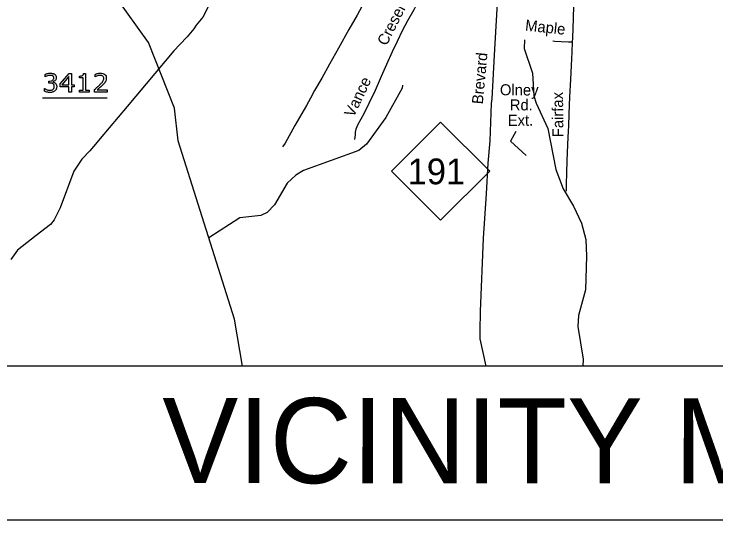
# Model space of a CAD drawing. Extents: x 925297 to 940193, y 663541 to 689899.
# Drawn here: x 927782 to 928734, y 687191 to 687878 of the extents above; entities that cross this region are included whole.
import ezdxf

# ---------------------------------------------------------------- set-up
doc = ezdxf.new("R2010")
doc.units = 0
doc.layers.add('Default', color=7, linetype='Continuous')
doc.layers.add('Sheet Title CELL', color=7, linetype='Continuous')

msp = doc.modelspace()

# ---------------------------------------------------------------- linework, layer by layer
at = {"layer": 'Default'}
msp.add_line((927820.41, 687764.45), (927908.02, 687764.45), dxfattribs=at)
for points in [[(928091.65, 687400.3), (928081, 687464), (928004.68, 687706.39), (927999.58, 687750.47), (927964.39, 687839.77), (927889.77, 687944.3), (927840.93, 688024.69), (927845.58, 688107.96), (927839.62, 688127.77), (927820.71, 688158.34), (927785.15, 688236.49), (927782.3, 688250.33)], [(928422.69, 687400.3), (928414.19, 687437.24), (928414.42, 687448.07), (928414.77, 687474.32), (928419.06, 687574.19), (928422.79, 687634.18), (928425.12, 687675.86), (928427.91, 687706.32), (928429.77, 687756.68), (928430.82, 687763.14), (928433.64, 687822.45), (928441.53, 687956.48), (928442.81, 687994.5), (928444.79, 688004.27), (928451.77, 688016.8), (928473.2, 688057.64), (928484.27, 688085)], [(928547.33, 688006.84), (928547.12, 688001.43), (928545.43, 687972.42), (928544.67, 687955.24), (928543.15, 687930.23), (928542.13, 687908.37), (928541.14, 687889.77), (928540.37, 687872.33), (928539.47, 687845.93), (928539.19, 687840.09)], [(928340.72, 687929.8), (928339.01, 687924.22), (928334.57, 687910.76), (928330.26, 687895.79), (928324.28, 687884), (928315.88, 687869.1), (928308.36, 687855.66), (928301.67, 687840.9), (928295.09, 687827.13), (928287.19, 687809.84), (928280.09, 687793.55), (928271.65, 687774.59), (928263.36, 687756.82), (928256.42, 687742.75), (928248.3, 687728.49), (928245.65, 687721.79), (928244.74, 687717.88), (928244.7, 687714.83), (928244.78, 687714.17), (928243.99, 687708.13)], [(928046.58, 687890.75), (928037.88, 687873.87), (928029, 687863.21), (928025.8, 687858.42), (928016.92, 687847.4), (928006.66, 687836.95), (927998.75, 687828.38), (927935.15, 687752.6), (927898.64, 687709.48), (927894.38, 687704.33), (927884.61, 687692.43), (927873.85, 687681.14), (927862.84, 687664.97), (927844.18, 687615.02), (927836.05, 687598.97), (927831.25, 687592.57), (927811.73, 687577.66), (927786.55, 687557.64), (927777.5, 687545.2)], [(928255.36, 687891.39), (928253.89, 687888.71), (928247.32, 687876.76), (928236.3, 687857.46), (928236.12, 687857.14), (928222.06, 687832), (928209.99, 687810.35), (928199.4, 687791.46), (928189.6, 687774.59), (928183.96, 687764.06), (928178.6, 687754.08), (928175.6, 687748.87)], [(928474.44, 687843.42), (928473.99, 687831.42), (928485.22, 687798.2), (928487.31, 687767.3), (928490.14, 687757.18), (928506.14, 687723), (928516.94, 687667.36), (928526.81, 687641), (928541.18, 687617.67), (928551.97, 687594.46), (928557.56, 687572.25), (928558.75, 687549.78), (928557.13, 687503.82), (928547.87, 687468.92), (928546.92, 687454.15), (928554.16, 687409.86), (928553.81, 687400.3)], [(928539.19, 687840.09), (928534.03, 687840.05), (928524.48, 687840.71), (928515.63, 687841.22), (928512.74, 687841.48)], [(928539.19, 687840.09), (928538.55, 687826.37), (928537.9, 687808.23), (928536.96, 687789.51), (928535.7, 687765.86), (928534.7, 687742.72), (928534, 687726.18)], [(927824.09, 687792.89), (927823.92, 687792.89), (927823.92, 687796.4)], [(927863.27, 687779.49), (927859.56, 687779.49), (927859.56, 687772.45), (927856.33, 687772.45), (927856.33, 687779.49), (927844.35, 687779.49), (927844.35, 687783.35), (927856.47, 687797.45), (927859.56, 687797.45), (927859.56, 687782.18), (927863.27, 687782.18), (927863.27, 687779.49)], [(927876.22, 687797.53), (927878.83, 687797.53), (927878.83, 687775), (927883.93, 687775), (927883.93, 687772.45)], [(927891.86, 687792.89), (927891.69, 687792.89), (927891.69, 687796.42)], [(927830.5, 687784.63), (927828.98, 687784.63), (927828.98, 687787.4), (927830.16, 687787.4)], [(927834.22, 687786.35), (927834.22, 687786.12)], [(927856.33, 687782.18), (927856.33, 687793.47), (927846.63, 687782.18), (927856.33, 687782.18)], [(927883.93, 687772.45), (927870.4, 687772.45), (927870.4, 687775), (927875.6, 687775), (927875.6, 687791.75), (927870.4, 687791.75), (927870.4, 687794.04)], [(927823.21, 687773.49), (927823.21, 687777), (927823.46, 687777)], [(927908.02, 687772.45), (927891.08, 687772.45), (927891.08, 687775.98)], [(928308.9, 687781.7), (928308.37, 687777.72), (928286.53, 687738.07), (928260.01, 687701.79), (928249.68, 687692.95), (928174.67, 687666.03), (928164.03, 687659.6), (928152.42, 687648.81), (928135.36, 687619.4), (928125.4, 687608.95), (928116.83, 687604.85), (928088.28, 687601.48), (928046.2, 687574.52)], [(927894.55, 687775.34), (927908.02, 687775.34), (927908.02, 687772.45)], [(928175.6, 687748.87), (928162.97, 687726.91), (928149.6, 687702.87), (928146.19, 687697.85)], [(928462.7, 687718.68), (928455.62, 687705.58), (928476.55, 687686.11)], [(928534, 687726.18), (928533.72, 687719.55), (928532.83, 687701.39), (928532.04, 687678.91), (928531.28, 687663.2), (928531.06, 687646.86), (928530.99, 687637.72)]]:
    msp.add_lwpolyline(points, dxfattribs=at)
msp.add_lwpolyline([(928294.08, 687665.11), (928360.68, 687731.71), (928427.28, 687665.11), (928360.68, 687598.51)], close=True, dxfattribs=at)
for points in [[(927823.92, 687796.4), (927825.11, 687796.99), (927827.11, 687797.48), (927829.1, 687797.98), (927830.96, 687797.98), (927832.8, 687797.98), (927834.19, 687797.64), (927835.59, 687797.3), (927836.71, 687796.57), (927837.92, 687795.76), (927838.54, 687794.62), (927839.17, 687793.47), (927839.17, 687791.95), (927839.17, 687789.86), (927837.69, 687788.31), (927836.22, 687786.75), (927834.22, 687786.35)], [(927830.16, 687787.4), (927832.72, 687787.4), (927834.24, 687788.47), (927835.76, 687789.54), (927835.76, 687791.59), (927835.76, 687792.5), (927835.37, 687793.18), (927834.98, 687793.87), (927834.3, 687794.3), (927833.57, 687794.74), (927832.75, 687794.91), (927831.92, 687795.08), (927830.88, 687795.08), (927829.28, 687795.08), (927827.49, 687794.51), (927825.69, 687793.94), (927824.09, 687792.89)], [(927870.4, 687794.04), (927871.46, 687794.04), (927872.67, 687794.21), (927873.87, 687794.39), (927874.5, 687794.73), (927875.27, 687795.14), (927875.71, 687795.79), (927876.16, 687796.44), (927876.22, 687797.53)], [(927891.08, 687775.98), (927892.84, 687777.49), (927894.62, 687779), (927896.39, 687780.51), (927897.93, 687782.01), (927901.16, 687785.13), (927902.35, 687786.96), (927903.55, 687788.8), (927903.55, 687790.93), (927903.55, 687792.88), (927902.26, 687793.98), (927900.97, 687795.08), (927898.66, 687795.08), (927897.13, 687795.08), (927895.34, 687794.54), (927893.56, 687794), (927891.86, 687792.89)], [(927891.69, 687796.42), (927892.88, 687797), (927894.87, 687797.49), (927896.87, 687797.98), (927898.73, 687797.98), (927902.58, 687797.98), (927904.77, 687796.12), (927906.95, 687794.27), (927906.95, 687791.1), (927906.95, 687789.67), (927906.59, 687788.44), (927906.23, 687787.21), (927905.53, 687786.1), (927904.87, 687785.06), (927903.99, 687784.05), (927903.11, 687783.04), (927901.85, 687781.82), (927900.05, 687780.06), (927898.13, 687778.41), (927896.22, 687776.75), (927894.55, 687775.34)], [(927834.22, 687786.12), (927835.03, 687785.98), (927836.07, 687785.55), (927837.11, 687785.13), (927837.83, 687784.49)], [(927837.83, 687784.49), (927838.64, 687783.76), (927839.16, 687782.67), (927839.68, 687781.58), (927839.68, 687779.85), (927839.68, 687778.13), (927839.06, 687776.71), (927838.43, 687775.28), (927837.31, 687774.22), (927836.05, 687773.04), (927834.35, 687772.48), (927832.64, 687771.91), (927830.61, 687771.91), (927828.53, 687771.91), (927826.51, 687772.41), (927824.5, 687772.9), (927823.21, 687773.49)], [(927823.46, 687777), (927824.89, 687776.06), (927826.82, 687775.43), (927828.75, 687774.81), (927830.55, 687774.81), (927831.61, 687774.81), (927832.81, 687775.17), (927834, 687775.52), (927834.74, 687776.21), (927835.51, 687776.95), (927835.89, 687777.84), (927836.27, 687778.74), (927836.27, 687780.1), (927836.27, 687781.45), (927835.84, 687782.33), (927835.41, 687783.21), (927834.65, 687783.72), (927833.9, 687784.24), (927832.82, 687784.44), (927831.74, 687784.63), (927830.5, 687784.63)]]:
    msp.add_open_spline(points, degree=3, dxfattribs=at)
at = {"layer": 'Sheet Title CELL'}
msp.add_line((927148.43, 687191.49), (930192.06, 687191.49), dxfattribs=at)
msp.add_lwpolyline([(927148.43, 689501.34), (930192.06, 689501.34), (930192.06, 687400.3), (927148.43, 687400.3)], close=True, dxfattribs=at)

# ---------------------------------------------------------------- texts
at = {"layer": 'Default'}
for s, rotation, p in [('Cresent', 63.19988, (928287.19, 687834.17)), ('Maple', 353.97374, (928474.85, 687855.85)), ('Brevard', 84.69022, (928417.88, 687755.42)), ('Vance', 64.59671, (928242.57, 687737.03)), ('Olney', 359.47288, (928441.07, 687768.06)), ('Fairfax', 90.69719, (928527.45, 687711.17)), ('Rd.', 0.01299, (928454.59, 687747.45)), ('Ext.', 0.09956, (928451.81, 687726.51))]:
    msp.add_text(s, height=15, rotation=rotation, dxfattribs=at).set_placement(p)
msp.add_text('191', height=35, dxfattribs=at).set_placement((928315.9, 687647.16))
at = {"layer": 'Sheet Title CELL'}
msp.add_text('VICINITY MAP', height=115.5015, rotation=359.9578, dxfattribs=at).set_placement((927982.9, 687241.61))

doc.saveas('drawing.dxf')
